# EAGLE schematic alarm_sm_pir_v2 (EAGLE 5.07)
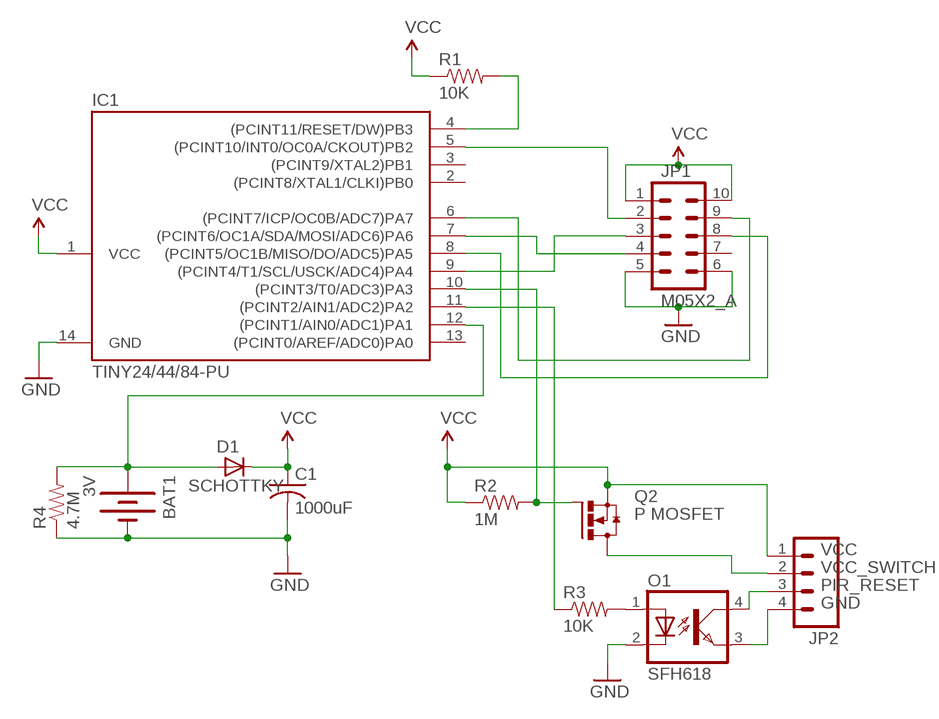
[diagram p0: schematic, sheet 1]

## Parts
BAT1  3V  BATTERYCR2302  [BATT_CR2032]
C1  1000uF  C-US100D  [C050-100D]
D1  SCHOTTKY  DIODE5MM  [DIODE5MM]
IC1  TINY24/44/84-PU  [DIL14]
JP1  M05X2_A  [2X05]
JP2  M04PTH  [1X04]
O1  SFH618  [DIP4-2]
Q2  P MOSFET  MOSFET_P_SMD_SOT23  [SUPER-SOT3]
R1  10K  RESISTOR5MM  [RESISTOR5MM]
R2  1M  RESISTOR5MM  [RESISTOR5MM]
R3  10K  RESISTOR5MM  [RESISTOR5MM]
R4  4.7M  RESISTOR5MM  [RESISTOR5MM]

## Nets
CE: IC1.5((PCINT10/INT0/OC0A/CKOUT)PB2) JP1.2
CSN: IC1.6((PCINT7/ICP/OC0B/ADC7)PA7) JP1.9
GND: BAT1.2(-) C1.2 IC1.14(GND) JP1.5 JP1.6 O1.2(C) R4.P$1
MI: IC1.7((PCINT6/OC1A/SDA/MOSI/ADC6)PA6) JP1.4
MO: IC1.8((PCINT5/OC1B/MISO/DO/ADC5)PA5) JP1.8
N$1: IC1.10((PCINT3/T0/ADC3)PA3) Q2.1(G) R2.P$2
N$4: O1.1(A) R3.P$2
N$6: BAT1.1(+) D1.P$2(A) IC1.12((PCINT1/AIN0/ADC1)PA1) R4.P$2
N$9: IC1.11((PCINT2/AIN1/ADC2)PA2) R3.P$1
N$12: JP2.2 Q2.3(D)
PIR_GND: JP2.4 O1.3(EMIT)
PIR_RESET: JP2.3 O1.4(COL)
RESET: IC1.4((PCINT11/RESET/DW)PB3) R1.P$2
SCK: IC1.9((PCINT4/T1/SCL/USCK/ADC4)PA4) JP1.3
VCC: C1.1 D1.P$1(C) IC1.1(VCC) JP1.1 JP1.10 JP2.1 Q2.2(S) R1.P$1 R2.P$1
Unconnected: IC1.2((PCINT8/XTAL1/CLKI)PB0) IC1.3((PCINT9/XTAL2)PB1) IC1.13((PCINT0/AREF/ADC0)PA0) JP1.7

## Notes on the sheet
- VCC
- VCC_SWITCH
- PIR_RESET
- GND

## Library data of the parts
BAT1 = SparkFun:BATTERY: Battery Holders
C1 = adafruit:C-US: CAPACITOR, American symbol
D1 = SparkFun:DIODE: Diode
IC1 = avr-5:TINY24/44/84
JP1 = SparkFun:M05X2_A
JP2 = SparkFun:M04: Header 4 Standard 4-pin 0.1" header. Use with straight break away headers (SKU : PRT-00116), right angle break away headers (PRT-00553), swiss pins (PRT-00743), machine pins (PRT-00117), and female headers (PRT-00115). Molex polarized connector foot print use with SKU : PRT-08231 with associated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
O1 = optocoupler:SFH618?*: Optocoupler, Phototransistor Output, Low Input Current Source: http://www.vishay.com/docs/83673/sfh618.pdf
Q2 = transistor-power:MOSFET_P_SMD_SOT23
R1-R4 = SparkFun:RESISTOR: Resistor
